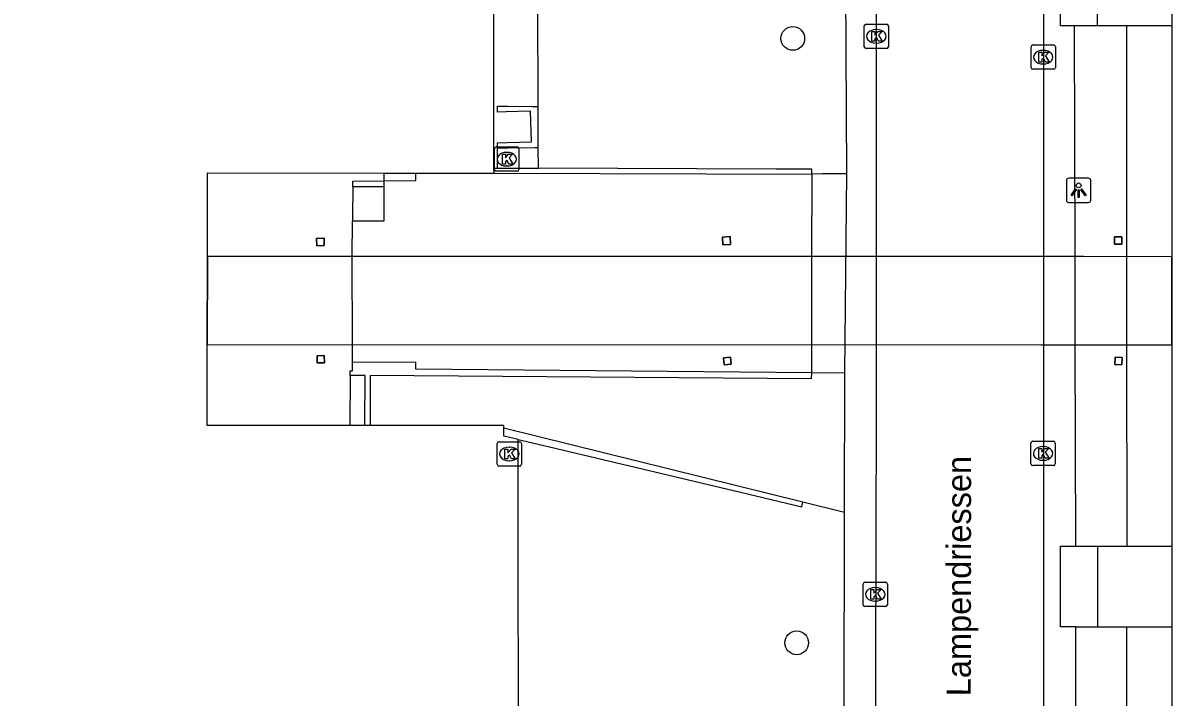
# Model space of a CAD drawing. Extents: x 161477 to 163040, y 383680 to 384868.
# Drawn here: x 161883.8 to 161931.1, y 384295.53 to 384323.26 of the extents above; entities that cross this region are included whole.
import ezdxf

# ---------------------------------------------------------------- set-up
doc = ezdxf.new("R2010")
doc.units = 0
for name, color, linetype in [('IMGEO_Boom', 7, 'Continuous'), ('IMGEO_Dek', 7, 'Continuous'), ('IMGEO_Groenvoorziening', 7, 'Continuous'), ('IMGEO_Kolk', 7, 'Continuous'), ('IMGEO_Lichtpunt', 7, 'Continuous'), ('IMGEO_Muur', 7, 'Continuous'), ('IMGEO_Openbare_ruimte_label', 7, 'Continuous'), ('IMGEO_Pand', 7, 'Continuous'), ('IMGEO_Pijler', 7, 'Continuous'), ('IMGEO_Rijbaan_lokaal_open', 7, 'Continuous'), ('IMGEO_Terreindeel_onvherhard', 7, 'Continuous'), ('IMGEO_Voetpad_gesloten', 7, 'Continuous'), ('IMGEO_Voetpad_op_trap', 7, 'Continuous'), ('IMGEO_Voetpad_open', 7, 'Continuous')]:
    doc.layers.add(name, color=color, linetype=linetype)

msp = doc.modelspace()

# ---------------------------------------------------------------- linework, layer by layer
at = {"layer": 'IMGEO_Boom'}
for centre in [(161915.49, 384322.63), (161915.65, 384297.76)]:
    msp.add_circle(centre, 0.489, dxfattribs=at)
at = {"layer": 'IMGEO_Dek'}
msp.add_lwpolyline([(161931.1, 384313.648), (161927.451, 384313.649), (161925.727, 384313.649), (161891.396, 384313.656), (161891.391, 384310.03), (161925.718, 384310.027), (161927.454, 384310.027), (161931.1, 384310.027)], close=True, dxfattribs=at)
at = {"layer": 'IMGEO_Groenvoorziening'}
for points in [[(161905.011, 384319.832), (161904.998, 384324.053)], [(161929.226, 384323.153), (161929.23, 384313.648), (161929.232, 384310.027), (161929.235, 384301.989), (161929.235, 384301.74)], [(161905.019, 384317.285), (161905.016, 384318.134)], [(161928.738, 384314.164), (161928.74, 384314.464), (161929.04, 384314.462), (161929.038, 384314.162), (161928.738, 384314.164)], [(161929.055, 384309.495), (161929.042, 384309.201), (161928.748, 384309.214), (161928.761, 384309.508), (161929.055, 384309.495)]]:
    msp.add_lwpolyline(points, dxfattribs=at)
at = {"layer": 'IMGEO_Kolk'}
for p, q in [((161918.43, 384322.289), (161918.43, 384323.141)), ((161918.505, 384323.215), (161919.357, 384323.215)), ((161919.431, 384323.141), (161919.431, 384322.289)), ((161918.918, 384322.995), (161918.943, 384322.995)), ((161919.357, 384322.215), (161918.505, 384322.215)), ((161918.941, 384322.435), (161918.916, 384322.435)), ((161925.298, 384321.433), (161925.298, 384322.285)), ((161925.373, 384322.359), (161926.225, 384322.359)), ((161926.299, 384322.285), (161926.299, 384321.433)), ((161925.786, 384322.139), (161925.811, 384322.139)), ((161926.225, 384321.359), (161925.373, 384321.359)), ((161925.809, 384321.579), (161925.784, 384321.579)), ((161903.219, 384317.236), (161903.219, 384318.088)), ((161903.294, 384318.162), (161904.146, 384318.162)), ((161903.707, 384317.942), (161903.732, 384317.942)), ((161904.22, 384318.088), (161904.22, 384317.236)), ((161904.146, 384317.162), (161903.294, 384317.162)), ((161903.73, 384317.382), (161903.705, 384317.382)), ((161903.322, 384305.105), (161903.322, 384305.957)), ((161903.397, 384306.031), (161904.249, 384306.031)), ((161903.81, 384305.811), (161903.835, 384305.811)), ((161904.323, 384305.957), (161904.323, 384305.105)), ((161925.293, 384305.125), (161925.293, 384305.977)), ((161925.368, 384306.051), (161926.22, 384306.051)), ((161925.781, 384305.831), (161925.806, 384305.831)), ((161926.294, 384305.977), (161926.294, 384305.125)), ((161903.833, 384305.251), (161903.808, 384305.251)), ((161925.804, 384305.271), (161925.779, 384305.271)), ((161904.249, 384305.031), (161903.397, 384305.031)), ((161926.22, 384305.051), (161925.368, 384305.051)), ((161918.385, 384299.326), (161918.385, 384300.178)), ((161918.46, 384300.252), (161919.312, 384300.252)), ((161918.873, 384300.032), (161918.898, 384300.032)), ((161919.386, 384300.178), (161919.386, 384299.326)), ((161919.312, 384299.252), (161918.46, 384299.252)), ((161918.896, 384299.472), (161918.871, 384299.472))]:
    msp.add_line(p, q, dxfattribs=at)
for points in [[(161918.43, 384322.289), (161918.43, 384323.141)], [(161918.505, 384323.215), (161919.357, 384323.215)], [(161919.431, 384323.141), (161919.431, 384322.289)], [(161918.751, 384322.915), (161918.874, 384322.915), (161918.874, 384322.764), (161919.004, 384322.915), (161919.168, 384322.915), (161919.022, 384322.764), (161919.175, 384322.515), (161919.023, 384322.515), (161918.938, 384322.679), (161918.874, 384322.612), (161918.874, 384322.515), (161918.751, 384322.515), (161918.751, 384322.915)], [(161919.357, 384322.215), (161918.505, 384322.215)], [(161925.298, 384321.433), (161925.298, 384322.285)], [(161925.373, 384322.359), (161926.225, 384322.359)], [(161926.299, 384322.285), (161926.299, 384321.433)], [(161925.619, 384322.059), (161925.742, 384322.059), (161925.742, 384321.908), (161925.872, 384322.059), (161926.036, 384322.059), (161925.89, 384321.908), (161926.043, 384321.659), (161925.891, 384321.659), (161925.806, 384321.823), (161925.742, 384321.756), (161925.742, 384321.659), (161925.619, 384321.659), (161925.619, 384322.059)], [(161926.225, 384321.359), (161925.373, 384321.359)], [(161903.219, 384317.236), (161903.219, 384318.088)], [(161903.294, 384318.162), (161904.146, 384318.162)], [(161904.22, 384318.088), (161904.22, 384317.236)], [(161903.54, 384317.862), (161903.663, 384317.862), (161903.663, 384317.711), (161903.793, 384317.862), (161903.957, 384317.862), (161903.811, 384317.711), (161903.964, 384317.462), (161903.812, 384317.462), (161903.727, 384317.626), (161903.663, 384317.559), (161903.663, 384317.462), (161903.54, 384317.462), (161903.54, 384317.862)], [(161904.146, 384317.162), (161903.294, 384317.162)], [(161903.322, 384305.105), (161903.322, 384305.957)], [(161903.397, 384306.031), (161904.249, 384306.031)], [(161903.643, 384305.731), (161903.766, 384305.731), (161903.766, 384305.58), (161903.896, 384305.731), (161904.06, 384305.731), (161903.914, 384305.58), (161904.067, 384305.331), (161903.915, 384305.331), (161903.83, 384305.495), (161903.766, 384305.428), (161903.766, 384305.331), (161903.643, 384305.331), (161903.643, 384305.731)], [(161904.323, 384305.957), (161904.323, 384305.105)], [(161925.293, 384305.125), (161925.293, 384305.977)], [(161925.368, 384306.051), (161926.22, 384306.051)], [(161925.614, 384305.751), (161925.737, 384305.751), (161925.737, 384305.6), (161925.867, 384305.751), (161926.031, 384305.751), (161925.885, 384305.6), (161926.038, 384305.351), (161925.886, 384305.351), (161925.801, 384305.515), (161925.737, 384305.448), (161925.737, 384305.351), (161925.614, 384305.351), (161925.614, 384305.751)], [(161926.294, 384305.977), (161926.294, 384305.125)], [(161904.249, 384305.031), (161903.397, 384305.031)], [(161926.22, 384305.051), (161925.368, 384305.051)], [(161918.385, 384299.326), (161918.385, 384300.178)], [(161918.46, 384300.252), (161919.312, 384300.252)], [(161918.706, 384299.952), (161918.829, 384299.952), (161918.829, 384299.801), (161918.959, 384299.952), (161919.123, 384299.952), (161918.977, 384299.801), (161919.13, 384299.552), (161918.978, 384299.552), (161918.893, 384299.716), (161918.829, 384299.649), (161918.829, 384299.552), (161918.706, 384299.552), (161918.706, 384299.952)], [(161919.386, 384300.178), (161919.386, 384299.326)], [(161919.312, 384299.252), (161918.46, 384299.252)]]:
    msp.add_lwpolyline(points, dxfattribs=at)
for centre, start, end in [((161918.507, 384323.139), 91.552, 178.448), ((161918.507, 384323.139), 91.552, 178.448), ((161919.355, 384323.139), 1.552, 88.448), ((161919.355, 384323.139), 1.552, 88.448), ((161918.507, 384322.291), 181.552, 268.448), ((161918.507, 384322.291), 181.552, 268.448), ((161919.355, 384322.291), 271.552, 358.448), ((161919.355, 384322.291), 271.552, 358.448), ((161925.375, 384322.283), 91.552, 178.448), ((161925.375, 384322.283), 91.552, 178.448), ((161926.223, 384322.283), 1.552, 88.448), ((161926.223, 384322.283), 1.552, 88.448), ((161925.375, 384321.435), 181.552, 268.448), ((161925.375, 384321.435), 181.552, 268.448), ((161926.223, 384321.435), 271.552, 358.448), ((161926.223, 384321.435), 271.552, 358.448), ((161903.296, 384318.086), 91.552, 178.448), ((161903.296, 384318.086), 91.552, 178.448), ((161904.144, 384318.086), 1.552, 88.448), ((161904.144, 384318.086), 1.552, 88.448), ((161903.296, 384317.238), 181.552, 268.448), ((161903.296, 384317.238), 181.552, 268.448), ((161904.144, 384317.238), 271.552, 358.448), ((161904.144, 384317.238), 271.552, 358.448), ((161903.399, 384305.955), 91.552, 178.448), ((161903.399, 384305.955), 91.552, 178.448), ((161904.247, 384305.955), 1.552, 88.448), ((161904.247, 384305.955), 1.552, 88.448), ((161925.37, 384305.975), 91.552, 178.448), ((161925.37, 384305.975), 91.552, 178.448), ((161926.218, 384305.975), 1.552, 88.448), ((161926.218, 384305.975), 1.552, 88.448), ((161903.399, 384305.107), 181.552, 268.448), ((161903.399, 384305.107), 181.552, 268.448), ((161904.247, 384305.107), 271.552, 358.448), ((161904.247, 384305.107), 271.552, 358.448), ((161925.37, 384305.127), 181.552, 268.448), ((161925.37, 384305.127), 181.552, 268.448), ((161926.218, 384305.127), 271.552, 358.448), ((161926.218, 384305.127), 271.552, 358.448), ((161918.462, 384300.176), 91.552, 178.448), ((161918.462, 384300.176), 91.552, 178.448), ((161919.31, 384300.176), 1.552, 88.448), ((161919.31, 384300.176), 1.552, 88.448), ((161918.462, 384299.328), 181.552, 268.448), ((161918.462, 384299.328), 181.552, 268.448), ((161919.31, 384299.328), 271.552, 358.448), ((161919.31, 384299.328), 271.552, 358.448)]:
    msp.add_arc(centre, 0.0765, start, end, dxfattribs=at)
for centre, major_axis, ratio, start_param, end_param in [((161918.917, 384322.715), (-0.387, 0.002), 0.722429, 4.712389, 7.853982), ((161918.942, 384322.715), (-0.39, 0.002), 0.717154, 1.570796, 4.712389), ((161925.785, 384321.859), (-0.387, 0.002), 0.722429, 4.712389, 7.853982), ((161925.81, 384321.859), (-0.39, 0.002), 0.717154, 1.570796, 4.712389), ((161903.706, 384317.662), (-0.387, 0.002), 0.722429, 4.712389, 7.853982), ((161903.731, 384317.662), (-0.39, 0.002), 0.717154, 1.570796, 4.712389), ((161903.809, 384305.531), (-0.387, 0.002), 0.722429, 4.712389, 7.853982), ((161903.834, 384305.531), (-0.39, 0.002), 0.717154, 1.570796, 4.712389), ((161925.78, 384305.551), (-0.387, 0.002), 0.722429, 4.712389, 7.853982), ((161925.805, 384305.551), (-0.39, 0.002), 0.717154, 1.570796, 4.712389), ((161918.872, 384299.752), (-0.387, 0.002), 0.722429, 4.712389, 7.853982), ((161918.897, 384299.752), (-0.39, 0.002), 0.717154, 1.570796, 4.712389)]:
    msp.add_ellipse(centre, major_axis=major_axis, ratio=ratio, start_param=start_param, end_param=end_param, dxfattribs=at)
at = {"layer": 'IMGEO_Lichtpunt'}
for p, q in [((161926.757, 384316.783), (161926.757, 384315.976)), ((161926.757, 384316.783), (161926.757, 384315.976)), ((161927.659, 384316.878), (161926.851, 384316.878)), ((161927.659, 384316.878), (161926.851, 384316.878)), ((161927.753, 384315.976), (161927.753, 384316.783)), ((161927.753, 384315.976), (161927.753, 384316.783)), ((161926.851, 384315.882), (161927.659, 384315.882)), ((161926.851, 384315.882), (161927.659, 384315.882))]:
    msp.add_line(p, q, dxfattribs=at)
for points in [[(161927.131, 384316.447), (161927.17, 384316.419), (161926.982, 384316.157), (161926.944, 384316.184), (161927.131, 384316.447)], [(161927.233, 384316.399), (161927.28, 384316.399), (161927.28, 384316.077), (161927.233, 384316.077), (161927.233, 384316.399)], [(161927.343, 384316.419), (161927.381, 384316.446), (161927.568, 384316.184), (161927.529, 384316.156), (161927.343, 384316.419)]]:
    msp.add_lwpolyline(points, dxfattribs=at)
msp.add_circle((161927.256, 384316.581), 0.0994, dxfattribs=at)
for centre, start, end in [((161926.851, 384316.783), 90, 180), ((161926.851, 384316.783), 90, 180), ((161927.659, 384316.783), 0, 90), ((161927.659, 384316.783), 0, 90), ((161926.851, 384315.976), 180, 270), ((161926.851, 384315.976), 180, 270), ((161927.659, 384315.976), 270, 0), ((161927.659, 384315.976), 270, 360)]:
    msp.add_arc(centre, 0.0946, start, end, dxfattribs=at)
at = {"layer": 'IMGEO_Muur'}
for points in [[(161903.34, 384318.108), (161903.34, 384318.328), (161903.734, 384318.34), (161904.733, 384318.369), (161904.695, 384319.637), (161903.696, 384319.608), (161903.34, 384319.597), (161903.341, 384319.844), (161903.755, 384319.841), (161904.749, 384319.834), (161905.011, 384319.832)], [(161905.016, 384318.134), (161905.011, 384319.832)], [(161905.016, 384318.134), (161904.869, 384318.131), (161903.778, 384318.115), (161903.34, 384318.108)], [(161898.671, 384316.77), (161898.668, 384317.09)], [(161898.671, 384316.77), (161899.972, 384316.778), (161899.972, 384317.088)], [(161903.179, 384317.291), (161903.339, 384317.29)], [(161903.202, 384317.083), (161916.272, 384317.049)], [(161903.339, 384317.29), (161905.019, 384317.285)], [(161916.272, 384317.049), (161916.273, 384317.249), (161914.803, 384317.254), (161905.019, 384317.285)], [(161897.376, 384316.522), (161897.376, 384316.762), (161898.671, 384316.77)], [(161898.674, 384316.52), (161897.376, 384316.522)], [(161898.674, 384316.52), (161898.671, 384316.77)], [(161897.269, 384308.755), (161897.266, 384308.955), (161897.366, 384308.957), (161897.365, 384309.128), (161897.363, 384309.296)], [(161916.255, 384308.862), (161899.974, 384309.016), (161899.974, 384309.077), (161899.973, 384309.306), (161897.363, 384309.296)], [(161897.882, 384306.702), (161897.885, 384308.763), (161897.269, 384308.755)], [(161916.255, 384308.862), (161916.253, 384308.622), (161898.095, 384308.763), (161898.092, 384306.702)], [(161903.592, 384306.612), (161915.906, 384303.561)], [(161904.193, 384306.123), (161904.95, 384305.944), (161913.333, 384303.956), (161915.857, 384303.357), (161915.906, 384303.561)]]:
    msp.add_lwpolyline(points, dxfattribs=at)
at = {"layer": 'IMGEO_Pand'}
for points in [[(161903.179, 384317.291), (161903.197, 384362.373), (161889.796, 384362.352), (161886.291, 384362.347), (161884.184, 384362.394), (161883.804, 384362.395)], [(161931.1, 384326.564), (161931.1, 384323.153)], [(161931.1, 384323.153), (161931.1, 384313.648), (161931.1, 384310.027), (161931.1, 384301.74)], [(161897.259, 384306.702), (161891.386, 384306.702), (161891.391, 384310.03), (161891.396, 384313.656), (161891.401, 384317.101), (161898.668, 384317.09)], [(161898.668, 384317.09), (161899.972, 384317.088)], [(161899.972, 384317.088), (161903.202, 384317.083)], [(161903.202, 384317.083), (161903.179, 384317.291)], [(161897.882, 384306.702), (161897.259, 384306.702)], [(161898.092, 384306.702), (161897.882, 384306.702)], [(161903.592, 384306.612), (161903.592, 384306.701), (161898.092, 384306.702)], [(161904.193, 384306.123), (161903.592, 384306.266), (161903.592, 384306.612)], [(161885.938, 384266.333), (161886.108, 384266.334), (161904.251, 384266.346), (161904.197, 384290.37), (161904.193, 384305.675), (161904.193, 384306.123)], [(161931.1, 384301.74), (161931.1, 384298.415)], [(161931.1, 384298.415), (161931.101, 384283.206)]]:
    msp.add_lwpolyline(points, dxfattribs=at)
at = {"layer": 'IMGEO_Pijler'}
for points in [[(161896.195, 384314.407), (161895.891, 384314.396), (161895.902, 384314.092), (161896.206, 384314.103)], [(161912.915, 384314.473), (161912.596, 384314.457), (161912.612, 384314.138), (161912.931, 384314.154)], [(161929.04, 384314.462), (161928.74, 384314.464), (161928.738, 384314.164), (161929.038, 384314.162)], [(161896.203, 384309.581), (161895.907, 384309.575), (161895.913, 384309.279), (161896.209, 384309.285)], [(161912.921, 384309.515), (161912.634, 384309.488), (161912.661, 384309.201), (161912.948, 384309.228)], [(161929.055, 384309.495), (161928.761, 384309.508), (161928.748, 384309.214), (161929.042, 384309.201)]]:
    msp.add_lwpolyline(points, close=True, dxfattribs=at)
at = {"layer": 'IMGEO_Rijbaan_lokaal_open'}
for points in [[(161918.826, 384264.809), (161918.941, 384307.313), (161918.941, 384310.028), (161918.941, 384313.65), (161918.941, 384368.88)], [(161925.81, 384368.885), (161925.81, 384313.649), (161925.81, 384310.027), (161925.81, 384259.31), (161918.844, 384259.31)]]:
    msp.add_lwpolyline(points, dxfattribs=at)
at = {"layer": 'IMGEO_Terreindeel_onvherhard'}
msp.add_lwpolyline([(161903.339, 384317.29), (161903.34, 384318.108)], dxfattribs=at)
at = {"layer": 'IMGEO_Voetpad_gesloten'}
msp.add_lwpolyline([(161931.1, 384313.648), (161927.451, 384313.649), (161925.727, 384313.649), (161891.396, 384313.656), (161891.391, 384310.03), (161925.718, 384310.027), (161927.454, 384310.027), (161931.1, 384310.027), (161931.1, 384313.648)], dxfattribs=at)
at = {"layer": 'IMGEO_Voetpad_op_trap'}
for points in [[(161928.04, 384323.153), (161927.082, 384323.153)], [(161927.144, 384301.74), (161928.04, 384301.74)], [(161927.145, 384298.415), (161928.04, 384298.415)]]:
    msp.add_lwpolyline(points, dxfattribs=at)
at = {"layer": 'IMGEO_Voetpad_open'}
for points in [[(161917.713, 384317.061), (161917.667, 384327.268)], [(161927.082, 384323.153), (161926.514, 384323.153), (161926.514, 384326.564), (161927.072, 384326.564)], [(161928.04, 384323.153), (161928.04, 384326.564)], [(161927.144, 384301.74), (161927.144, 384301.835), (161927.12, 384310.027), (161927.11, 384313.649), (161927.082, 384323.153)], [(161929.226, 384323.153), (161928.04, 384323.153)], [(161931.1, 384323.153), (161929.226, 384323.153)], [(161916.272, 384317.049), (161916.265, 384313.651), (161916.257, 384310.028), (161916.255, 384308.862)], [(161917.713, 384317.061), (161916.713, 384317.056), (161916.272, 384317.049)], [(161917.637, 384308.849), (161917.713, 384317.061)], [(161897.376, 384316.522), (161897.373, 384315.276), (161897.373, 384315.122)], [(161897.373, 384315.122), (161898.673, 384315.12), (161898.674, 384316.52)], [(161897.363, 384309.296), (161897.364, 384310.03), (161897.357, 384313.655), (161897.373, 384315.122)], [(161895.902, 384314.092), (161895.891, 384314.396), (161896.195, 384314.407), (161896.206, 384314.103), (161895.902, 384314.092)], [(161912.596, 384314.457), (161912.915, 384314.473), (161912.931, 384314.154), (161912.612, 384314.138), (161912.596, 384314.457)], [(161895.907, 384309.575), (161896.203, 384309.581), (161896.209, 384309.285), (161895.913, 384309.279), (161895.907, 384309.575)], [(161912.921, 384309.515), (161912.948, 384309.228), (161912.661, 384309.201), (161912.634, 384309.488), (161912.921, 384309.515)], [(161897.269, 384308.755), (161897.259, 384306.702)], [(161917.637, 384308.849), (161916.255, 384308.862)], [(161917.625, 384303.135), (161917.637, 384308.849)], [(161915.906, 384303.561), (161917.625, 384303.135)], [(161917.605, 384293.323), (161917.608, 384294.923), (161917.625, 384303.135)], [(161927.145, 384298.415), (161926.514, 384298.415), (161926.514, 384301.74), (161927.144, 384301.74)], [(161928.04, 384301.74), (161929.235, 384301.74)], [(161928.04, 384301.74), (161928.04, 384298.415)], [(161929.235, 384301.74), (161931.1, 384301.74)], [(161927.149, 384283.232), (161927.145, 384298.415)], [(161928.04, 384298.415), (161929.235, 384298.415)], [(161929.234, 384283.206), (161929.235, 384298.415)], [(161929.235, 384298.415), (161931.1, 384298.415)]]:
    msp.add_lwpolyline(points, dxfattribs=at)

# ---------------------------------------------------------------- texts
at = {"layer": 'IMGEO_Openbare_ruimte_label'}
msp.add_text('De Lampendriessen', height=1, rotation=89.9427, dxfattribs=at).set_placement((161922.817, 384293.481))

doc.saveas('drawing.dxf')
